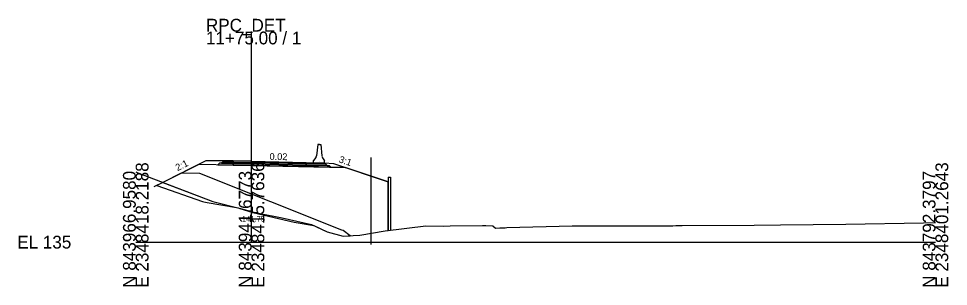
# Model space of a CAD drawing. Extents: x -26 to 2348728, y -10 to 843971.
# Drawn here: x 1274.3 to 1478.2, y -9.7 to 49 of the extents above; entities that cross this region are included whole.
import ezdxf

# ---------------------------------------------------------------- set-up
doc = ezdxf.new("R2010")
doc.units = 0
for name, color, linetype in [('Default', 7, 'Continuous'), ('Exist Cross Section Cell', 7, 'Continuous'), ('Exist XS Center Line Elevation Label', 7, 'Continuous'), ('Exist XS Ground Line', 7, 'Continuous'), ('Old_Level_1', 7, 'Continuous'), ('Prop CMT Pvmt Course 1', 7, 'Continuous'), ('Prop CMT Pvmt Course 2', 7, 'Continuous'), ('Prop CMT Pvmt Course 3', 7, 'Continuous'), ('Prop CMT Pvmt Surface', 7, 'Continuous'), ('Prop CMT Pvmt Surface Shoulder', 7, 'Continuous'), ('Prop CMT Shld Paved Course 1', 7, 'Continuous'), ('Prop CMT Shld Paved Course 2', 7, 'Continuous'), ('Prop CMT Shld Paved Course 3', 7, 'Continuous'), ('Prop CMT Slope Grass', 7, 'Continuous'), ('Prop CMT Subgrade Earthwork', 7, 'Continuous'), ('Prop XS Earthwork Shape', 7, 'Continuous'), ('Prop XS Retaining Wall', 7, 'Continuous'), ('Prop XS Side Slope Text', 7, 'Continuous'), ('Scratch_Level_6', 7, 'Continuous'), ('Typical Median Barrier CELL', 7, 'Continuous')]:
    doc.layers.add(name, color=color, linetype=linetype)

# ---------------------------------------------------------------- blocks, each defined once
blk = doc.blocks.new('TYPE T DOUBLE FACE BARRIER')
at = {"layer": 'Typical Median Barrier CELL'}
for p, q in [((-0.33, 3.83), (-0.6, 1.3)), ((0, 3.83), (-0.33, 3.83)), ((0, 3.83), (0.33, 3.83)), ((0.33, 3.83), (0.6, 1.3)), ((-0.75, 0.91), (-1.21, 0.25)), ((-1.21, -0.17), (-1.21, 0.25)), ((0, 0), (0, 0)), ((0.75, 0.91), (1.21, 0.25)), ((1.21, -0.17), (1.21, 0.25)), ((-1.21, -0.17), (1.21, -0.17))]:
    blk.add_line(p, q, dxfattribs=at)
for centre, start, end in [((-1.43, 1.38), 325.0039, 353.9447), ((1.43, 1.38), 186.0553, 214.9937)]:
    blk.add_arc(centre, 0.833, start, end, dxfattribs=at)

msp = doc.modelspace()

# ---------------------------------------------------------------- linework, layer by layer
at = {"layer": 'Exist Cross Section Cell'}
for p, q in [((1325.4, 0), (1325.4, 46.13)), ((1300, 0), (1325.4, 0)), ((1325.4, 0), (1475.4, 0))]:
    msp.add_line(p, q, dxfattribs=at)
at = {"layer": 'Exist XS Ground Line'}
msp.add_lwpolyline([(1300, 15.38), (1300.43, 15.21), (1316.89, 8.89), (1322.95, 7.38), (1325.4, 6.75), (1326.94, 6.36), (1332.11, 5.31), (1338.52, 3.85), (1342, 2.27), (1345.52, 1.28), (1347.72, 1.42), (1349.15, 1.53), (1354.68, 2.49), (1363.6, 3.55), (1367.49, 3.51), (1368.99, 3.57), (1376.02, 3.62), (1376.78, 3.62), (1378.31, 3.57), (1378.87, 3.08), (1379.83, 3.13), (1381.06, 3.17), (1381.38, 3.18), (1395.72, 3.58), (1400.02, 3.57), (1400.91, 3.56), (1416.61, 3.59), (1416.92, 3.59), (1417.26, 3.59), (1417.83, 3.6), (1418.46, 3.61), (1419.08, 3.64), (1419.86, 3.64), (1435.66, 3.75), (1441.43, 3.82), (1455.75, 3.96), (1472.8, 4.23), (1475.4, 4.27)], dxfattribs=at)
at = {"layer": 'Prop CMT Pvmt Course 1'}
for p, q in [((1321.4, 17.8), (1321.39, 17.55)), ((1325.4, 17.72), (1321.4, 17.8)), ((1321.4, 17.55), (1325.4, 17.47)), ((1325.39, 17.47), (1325.4, 17.72)), ((1325.39, 17.47), (1325.4, 17.72)), ((1325.39, 17.47), (1325.4, 17.6)), ((1325.4, 17.6), (1325.39, 17.47)), ((1325.39, 17.47), (1325.4, 17.6)), ((1325.4, 17.6), (1325.39, 17.47)), ((1325.39, 17.47), (1325.39, 17.47)), ((1325.39, 17.47), (1325.39, 17.47)), ((1325.4, 17.72), (1337.4, 17.48)), ((1325.4, 17.6), (1325.4, 17.6)), ((1325.4, 17.6), (1325.4, 17.6)), ((1337.4, 17.23), (1325.4, 17.47)), ((1337.4, 17.48), (1337.39, 17.23))]:
    msp.add_line(p, q, dxfattribs=at)
at = {"layer": 'Prop CMT Pvmt Course 2'}
for p, q in [((1321.39, 17.55), (1321.38, 17.22)), ((1325.4, 17.47), (1321.4, 17.55)), ((1321.4, 17.22), (1325.4, 17.14)), ((1325.38, 17.14), (1325.39, 17.47)), ((1325.38, 17.14), (1325.39, 17.47)), ((1325.4, 17.47), (1337.4, 17.23)), ((1337.4, 16.9), (1325.4, 17.14)), ((1337.39, 17.23), (1337.38, 16.9))]:
    msp.add_line(p, q, dxfattribs=at)
at = {"layer": 'Prop CMT Pvmt Course 3'}
for p, q in [((1321.38, 17.22), (1321.37, 16.89)), ((1325.4, 17.14), (1321.4, 17.22)), ((1321.4, 16.89), (1325.4, 16.81)), ((1325.37, 16.81), (1325.38, 17.14)), ((1325.37, 16.81), (1325.38, 17.14)), ((1325.4, 17.14), (1337.4, 16.9)), ((1337.4, 16.57), (1325.4, 16.81)), ((1337.38, 16.9), (1337.37, 16.57))]:
    msp.add_line(p, q, dxfattribs=at)
at = {"layer": 'Prop CMT Pvmt Surface'}
for q in [(1321.4, 17.8), (1337.4, 17.48)]:
    msp.add_line((1325.4, 17.72), q, dxfattribs=at)
at = {"layer": 'Prop CMT Pvmt Surface Shoulder'}
for p, q in [((1321.4, 17.8), (1319.4, 17.84)), ((1337.4, 17.48), (1341.4, 17.4))]:
    msp.add_line(p, q, dxfattribs=at)
at = {"layer": 'Prop CMT Shld Paved Course 1'}
for p, q in [((1319.4, 17.84), (1319.14, 17.6)), ((1319.14, 17.6), (1321.4, 17.55)), ((1321.4, 17.8), (1319.4, 17.84)), ((1321.39, 17.55), (1321.4, 17.8)), ((1337.39, 17.23), (1337.4, 17.48)), ((1337.4, 17.48), (1341.4, 17.4)), ((1341.64, 17.15), (1337.4, 17.23)), ((1341.4, 17.4), (1341.64, 17.15))]:
    msp.add_line(p, q, dxfattribs=at)
at = {"layer": 'Prop CMT Shld Paved Course 2'}
for p, q in [((1319.14, 17.6), (1318.79, 17.27)), ((1318.79, 17.27), (1321.4, 17.22)), ((1321.4, 17.55), (1319.14, 17.6)), ((1321.38, 17.22), (1321.39, 17.55)), ((1337.38, 16.9), (1337.39, 17.23)), ((1337.4, 17.23), (1341.64, 17.15)), ((1341.96, 16.81), (1337.4, 16.9)), ((1341.64, 17.15), (1341.96, 16.81))]:
    msp.add_line(p, q, dxfattribs=at)
at = {"layer": 'Prop CMT Shld Paved Course 3'}
for p, q in [((1318.34, 17.27), (1318, 16.95)), ((1318, 16.95), (1321.4, 16.89)), ((1318.79, 17.27), (1318.34, 17.27)), ((1321.4, 17.22), (1318.79, 17.27)), ((1321.37, 16.89), (1321.38, 17.22)), ((1337.37, 16.57), (1337.38, 16.9)), ((1337.4, 16.9), (1341.96, 16.81)), ((1342.76, 16.46), (1337.4, 16.57)), ((1341.96, 16.81), (1342.46, 16.78)), ((1342.46, 16.78), (1342.76, 16.46))]:
    msp.add_line(p, q, dxfattribs=at)
at = {"layer": 'Prop CMT Slope Grass'}
for p, q in [((1315.4, 17.8), (1305.97, 13.09)), ((1319.4, 17.84), (1315.4, 17.8)), ((1341.4, 17.4), (1343.4, 17.24)), ((1343.4, 17.24), (1355.4, 13.24)), ((1355.4, 13.24), (1355.4, 2.57))]:
    msp.add_line(p, q, dxfattribs=at)
at = {"layer": 'Prop CMT Subgrade Earthwork'}
for p, q in [((1321.4, 16.89), (1313.87, 17.04)), ((1325.4, 16.81), (1321.4, 16.89)), ((1325.4, 16.81), (1345.94, 16.39))]:
    msp.add_line(p, q, dxfattribs=at)
at = {"layer": 'Prop XS Earthwork Shape'}
msp.add_lwpolyline([(1326.94, 6.36), (1332.11, 5.31), (1338.52, 3.85), (1342, 2.27), (1345.52, 1.28), (1347.72, 1.42), (1349.15, 1.53), (1354.68, 2.49), (1355.4, 2.57), (1355.4, 13.24), (1345.94, 16.39), (1325.4, 16.81), (1321.4, 16.89), (1313.87, 17.04), (1305.97, 13.09), (1316.89, 8.89), (1322.95, 7.38), (1325.4, 6.75)], close=True, dxfattribs=at)
at = {"layer": 'Prop XS Retaining Wall'}
for p, q in [((1355.4, 14.24), (1355.4, 2.57)), ((1355.4, 14.24), (1355.9, 14.24)), ((1355.4, 14.24), (1355.4, 2.57)), ((1355.9, 14.24), (1355.9, 2.63))]:
    msp.add_line(p, q, dxfattribs=at)
at = {"layer": 'Scratch_Level_6'}
for p, q in [((1351.56, 18.55), (1351.56, -0.49)), ((1309.99, 15.1), (1305.97, 13.09)), ((1314.07, 15.06), (1309.99, 15.1)), ((1345.23, 2.59), (1314.07, 15.06)), ((1305.97, 13.09), (1303.99, 12.1)), ((1305.97, 13.09), (1304.64, 12.42)), ((1304.64, 12.42), (1314.65, 8.93)), ((1322.86, 7.4), (1325.68, 6.46)), ((1345.51, 2.53), (1345.23, 2.59)), ((1347.03, 1.38), (1345.51, 2.53))]:
    msp.add_line(p, q, dxfattribs=at)
for points in [[(1314.65, 8.93), (1314.97, 8.86), (1315.65, 8.7), (1322.11, 7.59)], [(1322.11, 7.59), (1322.5, 7.52), (1322.86, 7.4)], [(1325.68, 6.46), (1334.76, 4.37), (1339.04, 3.61)], [(1339.04, 3.61), (1342, 2.27), (1345.52, 1.28), (1347.03, 1.38)]]:
    msp.add_lwpolyline(points, dxfattribs=at)

# ---------------------------------------------------------------- block references
at = {"layer": 'Old_Level_1', "rotation": -1.1457628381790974}
msp.add_blockref('TYPE T DOUBLE FACE BARRIER', (1340.2, 17.59), dxfattribs=at)

# ---------------------------------------------------------------- texts
at = {"layer": 'Default'}
msp.add_text('0.02', height=1.5, rotation=358.8542, dxfattribs=at).set_placement((1329.34, 18.03))
at = {"layer": 'Exist Cross Section Cell'}
for s, p in [('RPC_DET', (1315.4, 46.13)), ('11+75.00 / 1', (1315.4, 43.33)), ('EL 135', (1274, -1.4))]:
    msp.add_text(s, height=2.8, dxfattribs=at).set_placement(p)
for s, p in [('E 2348418.2188', (1302.8, -10)), ('E 2348415.7636', (1328.2, -10)), ('E 2348401.2643', (1478.2, -10)), ('N 843966.9580', (1300, -10)), ('N 843941.6773', (1325.4, -10)), ('N 843792.3797', (1475.4, -10))]:
    msp.add_text(s, height=2.8, rotation=90, dxfattribs=at).set_placement(p)
at = {"layer": 'Exist XS Center Line Elevation Label'}
msp.add_text('141.75', height=1.2, dxfattribs=at).set_placement((1323.29, 4.51))
at = {"layer": 'Prop XS Side Slope Text'}
for s, rotation, p in [('3:1', 341.5668, (1344.44, 17.52)), ('2:1', 26.5651, (1309.17, 15.55))]:
    msp.add_text(s, height=1.5, rotation=rotation, dxfattribs=at).set_placement(p)

doc.saveas('drawing.dxf')
